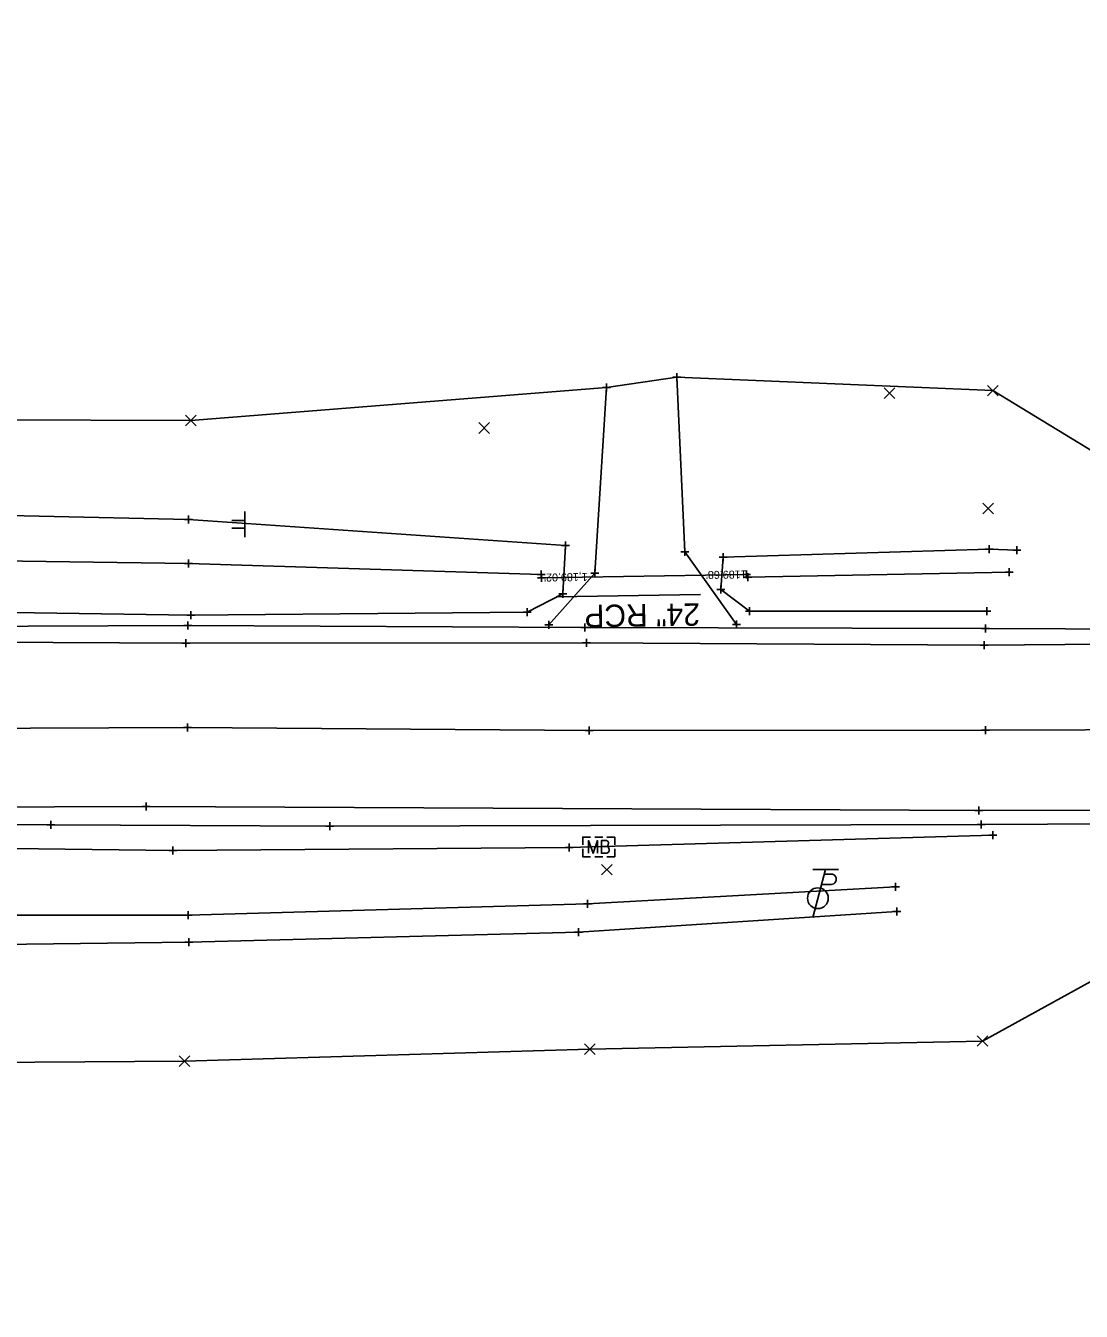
# Model space of a CAD drawing. Extents: x 2319153 to 2321514, y 575338 to 575500.
# Drawn here: x 2321092.9 to 2321224.8, y 575339 to 575499.6 of the extents above; entities that cross this region are included whole.
import ezdxf

# ---------------------------------------------------------------- set-up
doc = ezdxf.new("R2010")
doc.units = 0
for name, color, linetype in [('DR_X_Ditch', 7, 'Continuous'), ('DR_X_Elev_Flow', 7, 'Continuous'), ('DR_X_Storm_Sewer', 7, 'Continuous'), ('DR_X_Text', 7, 'Continuous'), ('PV_X_COP', 7, 'Continuous'), ('PV_X_Driveway', 7, 'Continuous'), ('PV_X_EOP', 7, 'Continuous'), ('PV_X_Shoulder', 7, 'Continuous'), ('RD_X_Cells', 7, 'Continuous'), ('SC_Scratch1', 7, 'Continuous'), ('SN_X_Public', 7, 'Continuous'), ('SV_X_Break_Lines', 7, 'Continuous'), ('SV_X_Random_Point', 7, 'Continuous'), ('SV_X_Shot_Marker', 7, 'Continuous'), ('SV_X_Terrain_Boundary', 7, 'Continuous'), ('UT_X_Misc_Cells', 7, 'Continuous')]:
    doc.layers.add(name, color=color, linetype=linetype)

msp = doc.modelspace()

# ---------------------------------------------------------------- linework, layer by layer
at = {"layer": 'DR_X_Ditch'}
for points in [[(2320984.82, 575432.18), (2321013.13, 575432.58), (2321062.77, 575433.12), (2321113.21, 575432.44), (2321157.3, 575431.05)], [(2321215.77, 575431.35), (2321183.14, 575430.73)], [(2321201.56, 575392.03), (2321163.08, 575389.89), (2321113.15, 575388.46), (2321064.26, 575388.47), (2321013.1, 575389.02), (2320998.47, 575389.29)]]:
    msp.add_lwpolyline(points, dxfattribs=at)
at = {"layer": 'DR_X_Elev_Flow'}
for p, q in [((2321182.97, 575431.56), (2321182.97, 575430.56)), ((2321156.82, 575430.65), (2321157.82, 575430.65)), ((2321157.32, 575431.15), (2321157.32, 575430.15)), ((2321157.32, 575430.65), (2321157.32, 575430.65)), ((2321182.47, 575431.06), (2321183.47, 575431.06)), ((2321182.97, 575431.06), (2321182.97, 575431.06))]:
    msp.add_line(p, q, dxfattribs=at)
at = {"layer": 'DR_X_Storm_Sewer'}
msp.add_line((2321182.97, 575431.06), (2321157.32, 575430.65), dxfattribs=at)
at = {"layer": 'DR_X_Text'}
msp.add_line((2321159.16, 575428.28), (2321177.21, 575428.57), dxfattribs=at)
at = {"layer": 'PV_X_COP'}
msp.add_lwpolyline([(2320664.58, 575411.98), (2320714.9, 575412.38), (2320764.67, 575412.55), (2320812.81, 575411.44), (2320863.71, 575412.31), (2320912.72, 575411.78), (2321003.29, 575411.48), (2321063.97, 575411.74), (2321113.08, 575411.94), (2321163.31, 575411.56), (2321212.82, 575411.61), (2321262.91, 575411.78), (2321313.37, 575411.56), (2321362.17, 575411.58), (2321412.59, 575412.78), (2321463.09, 575413.59), (2321512.4, 575413.87)], dxfattribs=at)
at = {"layer": 'PV_X_Driveway'}
for points in [[(2321181.72, 575424.81), (2321175.25, 575433.89), (2321174.26, 575455.72)], [(2321165.44, 575454.44), (2321163.98, 575431.23), (2321158.25, 575424.75)]]:
    msp.add_lwpolyline(points, dxfattribs=at)
at = {"layer": 'PV_X_EOP'}
for points in [[(2320664.7, 575422.48), (2320715.11, 575422.41), (2320765.04, 575422.04), (2320813.73, 575422.51), (2320875.77, 575422.41), (2320913.27, 575422.56), (2320963.52, 575422.63), (2321012.62, 575422.4), (2321063.13, 575422.74), (2321112.87, 575422.46), (2321162.94, 575422.5), (2321212.67, 575422.22), (2321263.07, 575422.64), (2321312.9, 575422.52), (2321362.03, 575422.99), (2321412.61, 575423.24), (2321462.61, 575423.66), (2321512.13, 575424.2)], [(2321512.27, 575403.63), (2321462.49, 575403.2), (2321412.87, 575402.74), (2321362.69, 575401.87), (2321312.5, 575402.02), (2321262.43, 575401.63), (2321211.98, 575401.55), (2321107.93, 575402.06), (2321016.27, 575401.73), (2320963.04, 575401.8), (2320913.34, 575401.45), (2320862.76, 575402.1), (2320813.85, 575401.67), (2320764.22, 575401.77), (2320714.4, 575401.87), (2320664.35, 575401.67)]]:
    msp.add_lwpolyline(points, dxfattribs=at)
at = {"layer": 'PV_X_Shoulder'}
for points in [[(2320664.52, 575424.33), (2320715.19, 575424.71), (2320764.98, 575424.15), (2320814.14, 575424.35), (2320863.42, 575424.12), (2320913.2, 575424.6), (2320963.28, 575424.88), (2321012.77, 575424.72), (2321063.18, 575424.45), (2321113.13, 575424.68), (2321162.73, 575424.41), (2321212.81, 575424.31), (2321262.9, 575424.09), (2321312.43, 575424.58), (2321362.34, 575425.06), (2321412.6, 575426.1), (2321462.14, 575426.29), (2321512.24, 575426.46)], [(2321513.03, 575401.02), (2321462.24, 575401.09), (2321412.23, 575401.08), (2321362.25, 575400.75), (2321312.5, 575400.39), (2321262.08, 575400.08), (2321212.3, 575399.81), (2321130.87, 575399.59), (2321095.99, 575399.76), (2321032.33, 575399.84), (2320996.03, 575397.56), (2320957.29, 575398.14), (2320912.73, 575400.28), (2320862.68, 575400.51), (2320815.54, 575400.3), (2320764.25, 575400.14), (2320714.58, 575400.4), (2320664.56, 575400.05)]]:
    msp.add_lwpolyline(points, dxfattribs=at)
at = {"layer": 'RD_X_Cells'}
for p, q in [((2321163.98, 575398.24), (2321164.98, 575398.24)), ((2321164.49, 575397.01), (2321164.49, 575397.01)), ((2321163.98, 575395.79), (2321164.98, 575395.79))]:
    msp.add_line(p, q, dxfattribs=at)
for points in [[(2321162.49, 575397.27), (2321162.49, 575398.24), (2321163.46, 575398.24)], [(2321163.19, 575396.21), (2321163.19, 575397.81), (2321163.77, 575396.21), (2321164.32, 575397.81), (2321164.32, 575396.21)], [(2321165.51, 575397.08), (2321165.57, 575397.15), (2321165.61, 575397.18), (2321165.63, 575397.22), (2321165.65, 575397.25), (2321165.67, 575397.3), (2321165.68, 575397.34), (2321165.71, 575397.42), (2321165.71, 575397.46), (2321165.71, 575397.51), (2321165.7, 575397.59), (2321165.67, 575397.65), (2321165.63, 575397.7), (2321165.57, 575397.75), (2321165.52, 575397.78), (2321165.5, 575397.79), (2321165.43, 575397.81), (2321164.82, 575397.81), (2321164.82, 575396.21), (2321165.51, 575396.21), (2321165.6, 575396.27), (2321165.67, 575396.33), (2321165.74, 575396.43), (2321165.77, 575396.54), (2321165.79, 575396.66), (2321165.79, 575396.73), (2321165.76, 575396.81), (2321165.71, 575396.92), (2321165.65, 575397), (2321165.51, 575397.08), (2321164.82, 575397.08)], [(2321165.49, 575398.24), (2321166.49, 575398.24), (2321166.49, 575397.27)], [(2321163.46, 575395.79), (2321162.49, 575395.79), (2321162.49, 575396.76)], [(2321166.49, 575396.76), (2321166.49, 575395.79), (2321165.49, 575395.79)]]:
    msp.add_lwpolyline(points, dxfattribs=at)
at = {"layer": 'SN_X_Public'}
for p, q in [((2321120.23, 575438.93), (2321120.23, 575435.73)), ((2321120.23, 575437.81), (2321118.63, 575437.81)), ((2321120.23, 575436.85), (2321118.63, 575436.85)), ((2321120.23, 575437.33), (2321120.23, 575437.33))]:
    msp.add_line(p, q, dxfattribs=at)
at = {"layer": 'SV_X_Break_Lines'}
msp.add_lwpolyline([(2321159.99, 575428.63), (2321160.35, 575434.67), (2321113.2, 575437.94), (2321062.77, 575439.07), (2321012.82, 575438.75), (2320979.25, 575437.35), (2320978.5, 575431.05), (2320984.41, 575426.56), (2321013.21, 575426.53), (2321063.26, 575426.7), (2321113.51, 575425.96), (2321155.53, 575426.35)], close=True, dxfattribs=at)
for points in [[(2321212.98, 575426.48), (2321183.32, 575426.45), (2321179.76, 575429.16), (2321180.06, 575433.22), (2321213.3, 575434.21), (2321216.73, 575434.08)], [(2321213.73, 575398.49), (2321160.8, 575396.95), (2321111.27, 575396.57), (2321060.79, 575397.2), (2321012.12, 575396.01), (2320996.2, 575393.81), (2320996.82, 575385.28), (2321014.07, 575385.28), (2321062.46, 575384.49), (2321113.23, 575385.1), (2321161.97, 575386.37), (2321201.76, 575388.95)]]:
    msp.add_lwpolyline(points, dxfattribs=at)
at = {"layer": 'SV_X_Random_Point'}
for p, q in [((2321200.17, 575453.05), (2321201.5, 575454.38)), ((2321200.17, 575454.38), (2321201.5, 575453.05)), ((2321213.09, 575453.36), (2321214.42, 575454.69)), ((2321213.09, 575454.69), (2321214.42, 575453.36)), ((2321112.84, 575449.64), (2321114.18, 575450.98)), ((2321112.84, 575450.98), (2321114.18, 575449.64)), ((2321149.49, 575448.69), (2321150.82, 575450.03)), ((2321149.49, 575450.03), (2321150.82, 575448.69)), ((2321212.48, 575438.62), (2321213.81, 575439.96)), ((2321212.48, 575439.96), (2321213.81, 575438.62)), ((2321164.85, 575393.5), (2321166.18, 575394.83)), ((2321164.85, 575394.83), (2321166.18, 575393.5)), ((2321162.69, 575371.05), (2321164.02, 575372.39)), ((2321162.69, 575372.39), (2321164.02, 575371.05)), ((2321211.8, 575372.09), (2321213.14, 575373.42)), ((2321211.8, 575373.42), (2321213.14, 575372.09)), ((2321112.04, 575369.56), (2321113.37, 575370.9)), ((2321112.04, 575370.9), (2321113.37, 575369.56))]:
    msp.add_line(p, q, dxfattribs=at)
at = {"layer": 'SV_X_Shot_Marker'}
for p, q in [((2321173.76, 575455.72), (2321174.76, 575455.72)), ((2321174.26, 575456.22), (2321174.26, 575455.22)), ((2321174.26, 575455.72), (2321174.26, 575455.72)), ((2321164.94, 575454.44), (2321165.94, 575454.44)), ((2321165.44, 575454.94), (2321165.44, 575453.94)), ((2321165.44, 575454.44), (2321165.44, 575454.44)), ((2321112.7, 575437.94), (2321113.7, 575437.94)), ((2321113.2, 575438.44), (2321113.2, 575437.44)), ((2321113.2, 575437.94), (2321113.2, 575437.94)), ((2321159.85, 575434.67), (2321160.85, 575434.67)), ((2321160.35, 575435.17), (2321160.35, 575434.17)), ((2321160.35, 575434.67), (2321160.35, 575434.67)), ((2321213.3, 575434.71), (2321213.3, 575433.71)), ((2321174.75, 575433.89), (2321175.75, 575433.89)), ((2321175.25, 575434.39), (2321175.25, 575433.39)), ((2321175.25, 575433.89), (2321175.25, 575433.89)), ((2321179.56, 575433.22), (2321180.56, 575433.22)), ((2321180.06, 575433.72), (2321180.06, 575432.72)), ((2321180.06, 575433.22), (2321180.06, 575433.22)), ((2321212.8, 575434.21), (2321213.8, 575434.21)), ((2321213.3, 575434.21), (2321213.3, 575434.21)), ((2321216.23, 575434.08), (2321217.23, 575434.08)), ((2321216.73, 575434.58), (2321216.73, 575433.58)), ((2321216.73, 575434.08), (2321216.73, 575434.08)), ((2321112.71, 575432.44), (2321113.71, 575432.44)), ((2321113.21, 575432.94), (2321113.21, 575431.94)), ((2321113.21, 575432.44), (2321113.21, 575432.44)), ((2321157.3, 575431.55), (2321157.3, 575430.55)), ((2321163.98, 575431.73), (2321163.98, 575430.73)), ((2321215.77, 575431.85), (2321215.77, 575430.85)), ((2321156.8, 575431.05), (2321157.8, 575431.05)), ((2321157.3, 575431.05), (2321157.3, 575431.05)), ((2321163.48, 575431.23), (2321164.48, 575431.23)), ((2321163.98, 575431.23), (2321163.98, 575431.23)), ((2321182.64, 575430.73), (2321183.64, 575430.73)), ((2321183.14, 575431.23), (2321183.14, 575430.23)), ((2321183.14, 575430.73), (2321183.14, 575430.73)), ((2321215.27, 575431.35), (2321216.27, 575431.35)), ((2321215.77, 575431.35), (2321215.77, 575431.35)), ((2321159.49, 575428.63), (2321160.49, 575428.63)), ((2321159.99, 575429.13), (2321159.99, 575428.13)), ((2321159.99, 575428.63), (2321159.99, 575428.63)), ((2321179.26, 575429.16), (2321180.26, 575429.16)), ((2321179.76, 575429.66), (2321179.76, 575428.66)), ((2321179.76, 575429.16), (2321179.76, 575429.16)), ((2321155.53, 575426.85), (2321155.53, 575425.85)), ((2321183.32, 575426.95), (2321183.32, 575425.95)), ((2321212.98, 575426.98), (2321212.98, 575425.98)), ((2321113.01, 575425.96), (2321114.01, 575425.96)), ((2321113.13, 575425.18), (2321113.13, 575424.18)), ((2321113.51, 575426.46), (2321113.51, 575425.46)), ((2321113.51, 575425.96), (2321113.51, 575425.96)), ((2321155.03, 575426.35), (2321156.03, 575426.35)), ((2321155.53, 575426.35), (2321155.53, 575426.35)), ((2321158.25, 575425.25), (2321158.25, 575424.25)), ((2321181.72, 575425.31), (2321181.72, 575424.31)), ((2321182.82, 575426.45), (2321183.82, 575426.45)), ((2321183.32, 575426.45), (2321183.32, 575426.45)), ((2321212.48, 575426.48), (2321213.48, 575426.48)), ((2321212.98, 575426.48), (2321212.98, 575426.48)), ((2321112.63, 575424.68), (2321113.63, 575424.68)), ((2321113.13, 575424.68), (2321113.13, 575424.68)), ((2321157.75, 575424.75), (2321158.75, 575424.75)), ((2321158.25, 575424.75), (2321158.25, 575424.75)), ((2321162.23, 575424.41), (2321163.23, 575424.41)), ((2321162.73, 575424.91), (2321162.73, 575423.91)), ((2321162.73, 575424.41), (2321162.73, 575424.41)), ((2321181.22, 575424.81), (2321182.22, 575424.81)), ((2321181.72, 575424.81), (2321181.72, 575424.81)), ((2321212.31, 575424.31), (2321213.31, 575424.31)), ((2321212.81, 575424.81), (2321212.81, 575423.81)), ((2321212.81, 575424.31), (2321212.81, 575424.31)), ((2321112.37, 575422.46), (2321113.37, 575422.46)), ((2321112.87, 575422.96), (2321112.87, 575421.96)), ((2321112.87, 575422.46), (2321112.87, 575422.46)), ((2321162.44, 575422.5), (2321163.44, 575422.5)), ((2321162.94, 575423), (2321162.94, 575422)), ((2321162.94, 575422.5), (2321162.94, 575422.5)), ((2321212.17, 575422.22), (2321213.17, 575422.22)), ((2321212.67, 575422.72), (2321212.67, 575421.72)), ((2321212.67, 575422.22), (2321212.67, 575422.22)), ((2321113.08, 575412.44), (2321113.08, 575411.44)), ((2321112.58, 575411.94), (2321113.58, 575411.94)), ((2321113.08, 575411.94), (2321113.08, 575411.94)), ((2321162.81, 575411.56), (2321163.81, 575411.56)), ((2321163.31, 575412.06), (2321163.31, 575411.06)), ((2321163.31, 575411.56), (2321163.31, 575411.56)), ((2321212.32, 575411.61), (2321213.32, 575411.61)), ((2321212.82, 575412.11), (2321212.82, 575411.11)), ((2321212.82, 575411.61), (2321212.82, 575411.61)), ((2321107.93, 575402.56), (2321107.93, 575401.56)), ((2321107.43, 575402.06), (2321108.43, 575402.06)), ((2321107.93, 575402.06), (2321107.93, 575402.06)), ((2321211.48, 575401.55), (2321212.48, 575401.55)), ((2321211.98, 575402.05), (2321211.98, 575401.05)), ((2321211.98, 575401.55), (2321211.98, 575401.55)), ((2321095.49, 575399.76), (2321096.49, 575399.76)), ((2321095.99, 575400.26), (2321095.99, 575399.26)), ((2321095.99, 575399.76), (2321095.99, 575399.76)), ((2321130.37, 575399.59), (2321131.37, 575399.59)), ((2321130.87, 575400.09), (2321130.87, 575399.09)), ((2321130.87, 575399.59), (2321130.87, 575399.59)), ((2321211.8, 575399.81), (2321212.8, 575399.81)), ((2321212.3, 575400.31), (2321212.3, 575399.31)), ((2321212.3, 575399.81), (2321212.3, 575399.81)), ((2321213.23, 575398.49), (2321214.23, 575398.49)), ((2321213.73, 575398.99), (2321213.73, 575397.99)), ((2321213.73, 575398.49), (2321213.73, 575398.49)), ((2321110.77, 575396.57), (2321111.77, 575396.57)), ((2321111.27, 575397.07), (2321111.27, 575396.07)), ((2321111.27, 575396.57), (2321111.27, 575396.57)), ((2321160.3, 575396.95), (2321161.3, 575396.95)), ((2321160.8, 575397.45), (2321160.8, 575396.45)), ((2321160.8, 575396.95), (2321160.8, 575396.95)), ((2321201.06, 575392.03), (2321202.06, 575392.03)), ((2321201.56, 575392.53), (2321201.56, 575391.53)), ((2321201.56, 575392.03), (2321201.56, 575392.03)), ((2321162.58, 575389.89), (2321163.58, 575389.89)), ((2321163.08, 575390.39), (2321163.08, 575389.39)), ((2321163.08, 575389.89), (2321163.08, 575389.89)), ((2321112.65, 575388.46), (2321113.65, 575388.46)), ((2321113.15, 575388.96), (2321113.15, 575387.96)), ((2321113.15, 575388.46), (2321113.15, 575388.46)), ((2321201.26, 575388.95), (2321202.26, 575388.95)), ((2321201.76, 575389.45), (2321201.76, 575388.45)), ((2321201.76, 575388.95), (2321201.76, 575388.95)), ((2321161.97, 575386.87), (2321161.97, 575385.87)), ((2321112.73, 575385.1), (2321113.73, 575385.1)), ((2321113.23, 575385.6), (2321113.23, 575384.6)), ((2321113.23, 575385.1), (2321113.23, 575385.1)), ((2321161.47, 575386.37), (2321162.47, 575386.37)), ((2321161.97, 575386.37), (2321161.97, 575386.37))]:
    msp.add_line(p, q, dxfattribs=at)
at = {"layer": 'SV_X_Terrain_Boundary'}
for points in [[(2321262.9, 575424.09), (2321213.75, 575454.03), (2321174.26, 575455.72), (2321165.44, 575454.44), (2321113.51, 575450.31), (2321063.39, 575450.45), (2321013.2, 575451.03), (2320972.82, 575455.47), (2320964.59, 575452.67), (2320952.83, 575453.45), (2320913.64, 575458.23), (2320857.66, 575474.67), (2320815.41, 575459.23), (2320777.59, 575499.63), (2320770.49, 575484.86), (2320769.15, 575483.51), (2320759.85, 575485.4), (2320758.6, 575484.73), (2320747.1, 575477.92), (2320738.56, 575481.4), (2320734.01, 575484.3), (2320722.62, 575480.62), (2320707.74, 575483.24), (2320663.9, 575465.47)], [(2320654.2, 575376.01), (2320714.52, 575366.13), (2320764.01, 575354.08), (2320802.52, 575338.98), (2320810.61, 575341.7), (2320812.62, 575342.69), (2320818.49, 575343.02), (2320821.03, 575342.66), (2320862.94, 575355.7), (2320914.29, 575368.22), (2320960.12, 575369.23), (2320978.33, 575368.17), (2321013.4, 575370.96), (2321062.8, 575369.91), (2321112.71, 575370.23), (2321163.35, 575371.72), (2321212.47, 575372.75), (2321262.08, 575400.08)]]:
    msp.add_lwpolyline(points, dxfattribs=at)
at = {"layer": 'UT_X_Misc_Cells'}
for p, q in [((2321192.84, 575394.2), (2321191.23, 575388.2)), ((2321194.44, 575394.2), (2321191.24, 575394.2)), ((2321192.68, 575393.6), (2321193.53, 575393.6)), ((2321192.34, 575392.33), (2321193.53, 575392.33))]:
    msp.add_line(p, q, dxfattribs=at)
msp.add_circle((2321191.88, 575390.6), 1.3, dxfattribs=at)
msp.add_arc((2321193.54, 575392.97), 0.638, 268.8767, 91.1233, dxfattribs=at)

# ---------------------------------------------------------------- texts
at = {"layer": 'DR_X_Text'}
msp.add_text('24" RCP', height=2.8, rotation=180.9024, dxfattribs=at).set_placement((2321177.11, 575427.46))
at = {"layer": 'SC_Scratch1'}
for s, p in [("1,189.02'", (2321163.1, 575431.25)), ("1189.68'", (2321182.96, 575431.56))]:
    msp.add_text(s, height=1, rotation=180.9024, dxfattribs=at).set_placement(p)

doc.saveas('drawing.dxf')
